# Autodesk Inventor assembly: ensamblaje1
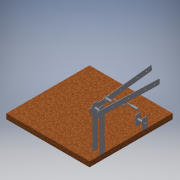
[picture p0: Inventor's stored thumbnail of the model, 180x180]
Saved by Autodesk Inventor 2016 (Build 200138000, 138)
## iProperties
Created: 2016-06
Part Number: ensamblaje1
Material: Genérico
Document SubType Name: Assembly
Designer: adm
Author: adm
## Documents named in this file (7)
- C:\Users\adm\Desktop\el ultimo\ensamblaje1.iam
- C:\Users\adm\Desktop\el ultimo\tablero.ipt
- C:\Users\adm\Desktop\el ultimo\soporte1.ipt
- C:\Users\adm\Desktop\el ultimo\eje metalico.ipt
- C:\Users\adm\Desktop\el ultimo\rodillo de movimiento.ipt
- C:\Users\adm\Desktop\el ultimo\soporte2.ipt
- C:\Users\adm\Desktop\el ultimo\tabla de rodillos.ipt
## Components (17 placed, 6 different names)
1. tablero:1 — Coincidencia:1, Coincidencia:2, Nivelación:1, Coincidencia:6, Coincidencia:7, Nivelación:3
2. soporte1:1 — Coincidencia:1, Nivelación:1, Nivelación:2, Coincidencia:5, Coincidencia:10
3. soporte1:2 — Coincidencia:2, Nivelación:2, Coincidencia:4, Tangente:4, Coincidencia:13
4. eje metalico:1 — Tangente:1, Insertar:3, Tangente:4, Tangente:5
5. eje metalico:2 — Coincidencia:8, Coincidencia:9, Tangente:2, Insertar:2
6. rodillo de movimiento:1 — Coincidencia:10, Coincidencia:11, Tangente:2
7. rodillo de movimiento:2 — Tangente:1, Coincidencia:4, Coincidencia:5
8. soporte2:1 — Coincidencia:6, Nivelación:3, Nivelación:4, Coincidencia:9, Coincidencia:12
9. soporte2:2 — Coincidencia:7, Nivelación:4, Coincidencia:8, Coincidencia:11
10. tabla de rodillos:1 — Insertar:2, Insertar:3, Insertar:4, Insertar:5, Insertar:6, Coincidencia:12
11. eje metalico:3 — Insertar:4, Insertar:7
12. eje metalico:4 — Insertar:5, Insertar:8
13. eje metalico:5 — Insertar:6, Insertar:9, Tangente:6
14. rodillo de movimiento:3 — Insertar:7
15. rodillo de movimiento:4 — Insertar:8
16. rodillo de movimiento:5 — Insertar:9
17. tabla de rodillos:2 — Tangente:5, Coincidencia:13, Tangente:6
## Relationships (29: Mate 12, Insert 8, Tangent 5, Flush 4)
- Coincidencia:1 [Mate]: tablero:1 ↔ soporte1:1
- Coincidencia:2 [Mate]: tablero:1 ↔ soporte1:2
- Nivelación:1 [Flush]: tablero:1 ↔ soporte1:1
- Nivelación:2 [Flush]: soporte1:1 ↔ soporte1:2
- Tangente:1: eje metalico:1 ↔ rodillo de movimiento:2
- Coincidencia:4 [Mate]: soporte1:2 ↔ rodillo de movimiento:2
- Coincidencia:5 [Mate]: soporte1:1 ↔ rodillo de movimiento:2
- Coincidencia:6 [Mate]: tablero:1 ↔ soporte2:1
- Coincidencia:7 [Mate]: tablero:1 ↔ soporte2:2
- Nivelación:3 [Flush]: tablero:1 ↔ soporte2:1
- Nivelación:4 [Flush]: soporte2:1 ↔ soporte2:2
- Coincidencia:8 [Mate]: eje metalico:2 ↔ soporte2:2
- Coincidencia:9 [Mate]: eje metalico:2 ↔ soporte2:1
- Coincidencia:10 [Mate]: soporte1:1 ↔ rodillo de movimiento:1
- Coincidencia:11 [Mate]: rodillo de movimiento:1 ↔ soporte2:2
- Tangente:2: eje metalico:2 ↔ rodillo de movimiento:1
- Insertar:2: eje metalico:2 ↔ tabla de rodillos:1
- Insertar:3: eje metalico:1 ↔ tabla de rodillos:1
- Insertar:4: tabla de rodillos:1 ↔ eje metalico:3
- Insertar:5: tabla de rodillos:1 ↔ eje metalico:4
- Insertar:6: tabla de rodillos:1 ↔ eje metalico:5
- Insertar:7: eje metalico:3 ↔ rodillo de movimiento:3
- Insertar:8: eje metalico:4 ↔ rodillo de movimiento:4
- Insertar:9: eje metalico:5 ↔ rodillo de movimiento:5
- Coincidencia:12 [Mate]: soporte2:1 ↔ tabla de rodillos:1
- Tangente:4: soporte1:2 ↔ eje metalico:1
- Tangente:5: eje metalico:1 ↔ tabla de rodillos:2
- Coincidencia:13 [Mate]: soporte1:2 ↔ tabla de rodillos:2
- Tangente:6: eje metalico:5 ↔ tabla de rodillos:2
